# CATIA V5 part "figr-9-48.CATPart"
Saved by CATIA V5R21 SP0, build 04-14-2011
Part number: Part1
Bounding box of the stored display mesh (mm): x -53.419 to 50, y -50 to 50, z -57.709 to 133.109
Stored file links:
  D:\CATIA V5R21 E-RESOURCES\CATIA-V5R21\catia-v5r21-prt\c09-catia-v5r20-prt\c09-catia-v5r21-figr-9-48.CATPart
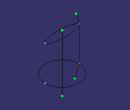
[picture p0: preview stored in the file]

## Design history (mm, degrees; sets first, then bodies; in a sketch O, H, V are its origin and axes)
Body1 (main body)
  Plane1: type Offset, RefPlane xy-plane, Offset 103
  Sketch1 on Plane1, origin (0, 0, 103), H (1, 0, 0), V (0, 1, 0)
    ellipse A1 centre (0, 0) semi-axes 50, 13.2069 rotation 0
    point P1 (50, 0)
    "Radius" A1 = 50
    coincidence: P1 H, A1 P1
  Extremum1: Reference Sketch1, Direction (1, 2, 3)
  Sketch2 on xy-plane, origin (0, 0, 0), H (1, 0, 0), V (0, 1, 0)
    circle A1 centre (0, 0) radius 50
    radius A1 = 50
  Extremum2: Reference Sketch2, Direction (1, 2, 3)
  Sketch3 on zx-plane, origin (0, 0, 0), H (-1, 0, 0), V (0, 0, 1)
    spline S1 through (37.7591, -31.0289) (41.8235, -21.251) (50, 0) (49.8084, 85.7657) (50, 103) (41.6255, 133.1089)
    reference projected line E1 (-50, 103) -> (50, 103) from Sketch1.A1
    point P1 (50, 0)
    point P2 (50, 103)
    distance V P1 = 50
    distance P2 V = 50
    coincidence: P1 H, P2 E1
  Sketch4 on zx-plane, origin (0, 0, 0), H (-1, 0, 0), V (0, 0, 1)
    line L1 (0, 111.062) -> (0, -57.7094)
    point P1 (0, 111.062)
    coincidence: P1 V
    vertical: L1 V
  Loft1: solid, Spine Sketch4, Guides Sketch3, Sections (Sketch1; Sketch2)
